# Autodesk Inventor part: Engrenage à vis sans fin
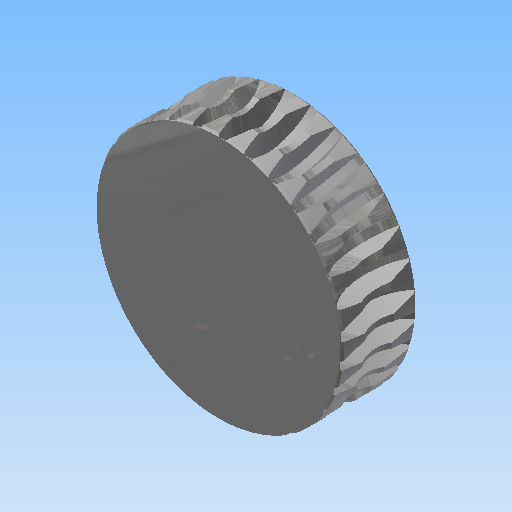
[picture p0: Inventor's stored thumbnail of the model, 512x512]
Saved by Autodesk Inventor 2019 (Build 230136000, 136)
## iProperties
Created: 2023-04
Part Number: Engrenage à vis sans fin
Material: Steel, Mild
Document SubType Name: Modeling
Designer: Thier
Categories: <?xml version="1.0" encoding="UTF-16"?> <MemberInstance><Categories><FamilyTemplate><FamilyTemplateParameter ValueType="xs:double" Id="1" ObjectReferenceKey="da
Density: 7.86 g/cm^3
Appearance: Steel
CustomPartVersion: 1
Author: Thier
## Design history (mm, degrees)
body "Solid1"
node "Plan de la dent"
sketch "Esquisse du corps de base"
  geometry: L1 (0, -11.2)-(0, 11.2) reference; L2 (0, 10)-(32.6, 10); L3 (32.6, 10)-(33, 9.459); L4 (-9.6, 0)-(57.6, 0) reference; L5 (33, 9.459)-(33, -9.459); L6 (0, -10)-(32.6, -10); L7 (0, 10)-(0, -10); L8 (32.6, -10)-(33, -9.459); C1 r 8 at (40, 0)
  constraints: 14 end point, 3 symmetric about line, 2 perpendicular, 2 point on line, 1 centre point, 1 collinear
  dimensions: "d50" = 53.4986 deg angle of L3 L2 (= da_fi); "d87" = 66 diameter of L5 L1 (= da_dae); "d89" = 16 diameter of C1 (= 2 x da_aw - da_da); "d92" = 20 distance of L2.start L6.start (= da_b); "d93" = 40 distance from line of C1.centre L7 (= da_aw)
revolve "Corps de base" stored, may be unused: angle "d35" = 90 deg
revolve "Corps de base 2" stored, may be unused: angle "d90" = 90 deg
workplane "Work Plane13"
revolve "Dent" stored, may be unused: angle "d43" = 90 deg
pattern_circular "Motif de la dent" dims angle "d46" = 360 deg
workplane "Work Plane14"
workplane "Work Plane15"
sketch "Esquisse de la dent"
  geometry: L1 (10, 3.862)-(10, -3.862) reference; L2 (-32.48, 0)-(-15.12, 0) reference; L3 (-30, 2.758)-(-30, -2.758); L4 (-30, -2.758)-(-22.4, -2.758); L5 (-22.4, -2.758)-(-17.6, -1.011); L6 (-17.6, -1.011)-(-17.6, 0); L7 (-17.6, 1.011)-(-22.4, 2.758); L8 (-22.4, 2.758)-(-30, 2.758); L9 (-17.6, 1.011)-(-17.6, 0); L10 (-20, 0)-(-20, -1.885)
  constraints: 16 end point, 4 perpendicular, 3 equal length, 2 point on line, 1 midpoint, 1 parallel, 1 vertical
  dimensions: "d38" = 40 distance between parallel lines of L1 L3 (= da_aw); "d39" = 20 deg angle of L7 L8 (= da_alfat); "d40" = 7.6 distance of L7.end L3.start (= 0.5 x da_df1); "d41" = 10 distance between parallel lines of L3 L10 (= 0.5 x da_d1); "d42" = 1.88496 distance of L10.start L10.end (= 0.3 x da_px)
sketch "Sketch8"
  geometry: C1 r 32.6 at (0, 0) reference; C2 r 30 at (0, 0)
  constraints: 1 centre point, 1 coincident
  dimensions: "d77" = 60 diameter of C2 (= da_dw)
body "Srf1"
feature "Diamètre primitif" dims "d78" = 20 (= da_b), "d79" = 0
other parameters: "da_aw" = 40 [user parameter; used in 5 equation terms], "da_fi" = 53.4986 deg [user parameter; used in 1 equation term], "da_b" = 20 [user parameter; used in 2 equation terms], "da_df" = 55.2 [user parameter], "da_da" = 64 [user parameter; used in 1 equation term], "da_beta" = 0.99669 [user parameter; used in 1 equation term], "da_alfat" = 20 deg [user parameter; used in 1 equation term], "da_df1" = 15.2 [user parameter; used in 1 equation term], "da_da1" = 24 [user parameter], "da_px" = 36 deg [user parameter; used in 1 equation term], "d37" = -0.99669 (computed from da_rightdir, da_beta), "d69" = 0, "d73" = 0, "d75" = 6 deg (computed from da_z), "da_dw" = 60 [user parameter; used in 1 equation term], "da_rightdir" = 0 [user parameter; used in 1 equation term], "d80" = 0, "d81" = 0, "d82" = 0, "d83" = 6 deg (computed from da_z), "d84" = 0, "d85" = 180 deg, "da_dae" = 66 [user parameter; used in 1 equation term]
